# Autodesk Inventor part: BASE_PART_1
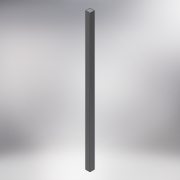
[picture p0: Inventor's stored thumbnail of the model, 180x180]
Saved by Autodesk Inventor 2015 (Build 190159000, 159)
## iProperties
Created: 2014-08
Part Number: BASE_PART_1
Material: Steel, Mild
Document SubType Name: Modeling
Designer: lakshayg
Density: 7.85 g/cm^3
Appearance: Semi-Polished
Mass: 430.682 g
Surface Area: 185.76 cm^2
Volume: 54.864 cm^3
Author: lakshayg
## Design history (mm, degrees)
sketch "Sketch1"
  geometry: L1 (0, 0)-(-12, 0); L2 (-12, 0)-(-12, -381); L3 (-12, -381)-(0, -381); L4 (0, -381)-(0, 0)
  constraints: 8 end point, 2 parallel, 1 horizontal, 1 perpendicular
  dimensions: "d0" = 381 distance of L3.end L1.start; "d1" = 12 distance of L1.start L1.end
extrude "Extrusion1" new body sketch "Sketch1" distance "d2" = 12; taper "d3" = 0 deg
body "Solid1"
